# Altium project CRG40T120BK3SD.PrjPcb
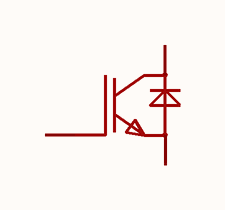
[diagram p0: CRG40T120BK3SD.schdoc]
1 sheet, 1 parts. Net scope: global (net labels, ports and power ports of the same name join across sheets).

## Sheet CRG40T120BK3SD.schdoc
size 127 x 101 mm

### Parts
Q?  crg40t120bk3sd  [TO-247-3_L15.8-W5.0-P5.44-L]  (value not drawn)

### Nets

Not connected (* = marked no-connect by the designer): Q? 1(G) 2(C) 3(E)

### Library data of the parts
Q? = crg40t120bk3sd: IGBT类型:-;耗散功率(Pd):278W;集射极击穿电压(Vces):1.2kV;集电极电流(Ic):40A;; Manufacturer: CRMICRO(华润微); AddInBom: yes; ModelId: 2dc33f6e48bd44aa838c2b9e2b85eb16; ModelTransform: 622.04631,185.078,0,0,0,0,-0.003,13.778,-196.85; Pd - Power Dissipation: 278W; Collector-Emitter Breakdown Voltage (Vces): 1.2kV; Current - Collector(Ic): 40A; Current - Collector Pulsed (Icm): 160A; Vce Saturation(VCE(sat)): 2.4V@40A,15V; Gate-Emitter Threshold Voltage (Vge(th)@Ic): 4.5V@250uA; Gate Charge(Qg): 239nC@15V; Input Capacitance(Cies): 3.823nF; Output Capacitance(Coes): 170pF; Reverse Transfer Capacitance (Cres): 94pF; Td(on): 62ns; Td(off): 265ns; Turn-On Energy (Eon): 3.3mJ; Switching Energy(Eoff): 1.4mJ; Reverse Recovery Time(trr): 88ns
